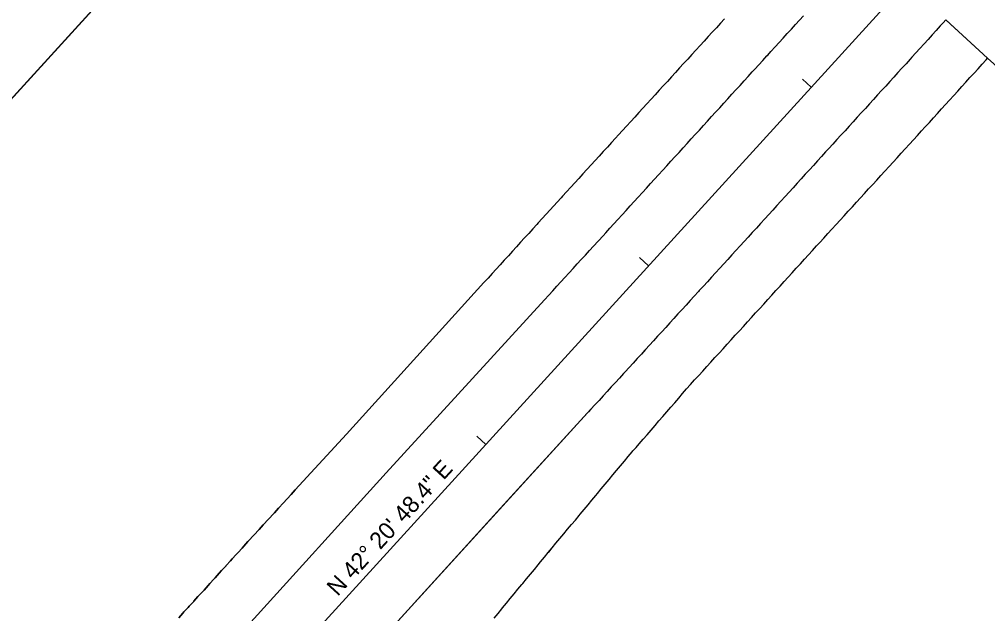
# Model space of a CAD drawing. Extents: x 1807040 to 1808827, y 913493 to 915218.
# Drawn here: x 1807609.2 to 1808009.9, y 913761.8 to 914007.6 of the extents above; entities that cross this region are included whole.
import ezdxf

# ---------------------------------------------------------------- set-up
doc = ezdxf.new("R2010")
doc.units = 0
for name, color, linetype in [('Old_Level_18', 7, 'Continuous'), ('Prop Dimension', 7, 'Continuous'), ('Prop EOT', 7, 'Continuous'), ('Prop Horizontal Alignment Direction Label', 7, 'Continuous'), ('Prop Horizontal Alignment Tick Small', 7, 'Continuous'), ('Scratch_Level_0', 7, 'Continuous'), ('Scratch_Level_1', 7, 'Continuous'), ('Scratch_Level_3', 7, 'Continuous')]:
    doc.layers.add(name, color=color, linetype=linetype)

msp = doc.modelspace()

# ---------------------------------------------------------------- linework, layer by layer
at = {"layer": 'Old_Level_18'}
msp.add_line((1808438.77, 914888.63), (1807428.35, 913780.01), dxfattribs=at)
at = {"layer": 'Prop Dimension'}
msp.add_line((1808082.8, 913925.07), (1808009.86, 913991.55), dxfattribs=at)
at = {"layer": 'Prop EOT'}
for p, q in [((1808009.86, 913991.55), (1807992.66, 914007.23)), ((1807683.94, 913668.92), (1807845.7, 913846.32))]:
    msp.add_line(p, q, dxfattribs=at)
for points in [[(1807900.98, 914007.89), (1807899.29, 914006.04), (1807897.61, 914004.19), (1807895.92, 914002.35), (1807894.24, 914000.5), (1807892.55, 913998.65), (1807890.87, 913996.81), (1807889.12, 913994.89), (1807887.44, 913993.04), (1807885.75, 913991.2), (1807884.07, 913989.35), (1807882.38, 913987.51), (1807880.7, 913985.66), (1807879.01, 913983.81), (1807877.33, 913981.97), (1807875.64, 913980.12), (1807873.95, 913978.27), (1807872.27, 913976.43), (1807870.58, 913974.58), (1807868.9, 913972.73), (1807867.21, 913970.89), (1807865.53, 913969.04), (1807863.84, 913967.19), (1807862.16, 913965.35), (1807860.47, 913963.5), (1807858.79, 913961.65), (1807857.1, 913959.81), (1807855.88, 913958.46), (1807854.19, 913956.62), (1807852.5, 913954.77), (1807850.82, 913952.93), (1807849.13, 913951.08), (1807847.45, 913949.23), (1807845.76, 913947.39), (1807844.07, 913945.54), (1807842.39, 913943.7), (1807840.7, 913941.85), (1807839.02, 913940), (1807837.33, 913938.16), (1807835.64, 913936.31), (1807833.96, 913934.47), (1807833.41, 913933.86)], [(1807992.51, 914007.37), (1807991.45, 914006.21), (1807990.25, 914004.89), (1807988.57, 914003.04), (1807986.89, 914001.19), (1807985.21, 913999.33), (1807983.53, 913997.48), (1807981.85, 913995.63), (1807980.17, 913993.78), (1807978.49, 913991.93), (1807977.77, 913991.14), (1807976.09, 913989.29), (1807974.41, 913987.44), (1807972.72, 913985.59), (1807971.04, 913983.75), (1807969.36, 913981.9), (1807967.67, 913980.05), (1807965.99, 913978.2), (1807964.31, 913976.35), (1807962.62, 913974.51), (1807960.94, 913972.66), (1807959.26, 913970.81), (1807957.57, 913968.96), (1807955.89, 913967.11), (1807954.21, 913965.26), (1807952.52, 913963.42), (1807950.84, 913961.57), (1807949.16, 913959.72), (1807947.47, 913957.87), (1807945.79, 913956.02), (1807944.11, 913954.17), (1807942.83, 913952.78), (1807941.15, 913950.93), (1807939.47, 913949.08), (1807937.79, 913947.23), (1807936.1, 913945.38), (1807934.42, 913943.53), (1807932.74, 913941.68), (1807931.06, 913939.83), (1807929.37, 913937.98), (1807927.69, 913936.13), (1807926.01, 913934.29), (1807924.33, 913932.44), (1807922.64, 913930.59), (1807920.96, 913928.74), (1807919.28, 913926.89), (1807917.6, 913925.04), (1807915.91, 913923.19), (1807915.84, 913923.11), (1807914.16, 913921.27), (1807912.47, 913919.42), (1807910.78, 913917.57), (1807909.1, 913915.73), (1807907.41, 913913.88), (1807905.73, 913912.04), (1807904.04, 913910.19), (1807902.36, 913908.34), (1807900.67, 913906.5), (1807898.98, 913904.65), (1807897.3, 913902.81), (1807895.61, 913900.96), (1807893.93, 913899.11), (1807892.24, 913897.27), (1807890.55, 913895.42), (1807890.16, 913894.99), (1807888.47, 913893.14), (1807886.79, 913891.29), (1807885.1, 913889.45), (1807883.41, 913887.6), (1807881.73, 913885.75), (1807880.04, 913883.91), (1807878.36, 913882.06), (1807876.67, 913880.21), (1807874.99, 913878.37), (1807873.3, 913876.52), (1807871.62, 913874.67), (1807869.93, 913872.83), (1807868.25, 913870.98), (1807866.56, 913869.13), (1807864.88, 913867.29), (1807863.19, 913865.44), (1807861.51, 913863.59), (1807859.82, 913861.75), (1807859.2, 913861.07), (1807857.51, 913859.22), (1807855.82, 913857.38), (1807854.14, 913855.54), (1807852.45, 913853.69), (1807850.76, 913851.85), (1807849.07, 913850), (1807847.38, 913848.16), (1807845.7, 913846.32), (1807844.74, 913845.29)], [(1807850.7, 913918.1), (1807851.83, 913919.34), (1807853.53, 913921.2), (1807855.21, 913923.05), (1807856.89, 913924.89), (1807858.58, 913926.74), (1807860.26, 913928.59), (1807861.95, 913930.44), (1807863.63, 913932.28), (1807865.31, 913934.13), (1807867, 913935.98), (1807868.68, 913937.83), (1807870.37, 913939.68), (1807872.05, 913941.52), (1807873.73, 913943.37), (1807875.42, 913945.22), (1807877.1, 913947.07), (1807878.79, 913948.91), (1807880.47, 913950.76), (1807882.15, 913952.61), (1807883.84, 913954.46), (1807885.52, 913956.31), (1807887.21, 913958.15), (1807888.89, 913960), (1807890.57, 913961.85), (1807892.26, 913963.7), (1807893.94, 913965.54), (1807895.63, 913967.39), (1807897.31, 913969.24), (1807898.99, 913971.09), (1807900.68, 913972.93), (1807902.36, 913974.78), (1807904.05, 913976.63), (1807905.73, 913978.48), (1807907.41, 913980.33), (1807909.1, 913982.17), (1807910.78, 913984.02), (1807912.47, 913985.87), (1807913.46, 913986.96), (1807915.15, 913988.81), (1807916.83, 913990.66), (1807918.52, 913992.51), (1807920.2, 913994.35), (1807921.89, 913996.2), (1807923.57, 913998.05), (1807925.26, 913999.89), (1807926.94, 914001.74), (1807928.63, 914003.59), (1807930.31, 914005.44), (1807931.99, 914007.28), (1807933.68, 914009.13)], [(1807863.1, 913829.08), (1807864.37, 913830.44), (1807865.68, 913832.01), (1807867.31, 913833.9), (1807868.95, 913835.79), (1807870.58, 913837.68), (1807872.22, 913839.57), (1807873.85, 913841.47), (1807875.49, 913843.36), (1807877.12, 913845.25), (1807878.76, 913847.14), (1807880.39, 913849.03), (1807882.02, 913850.92), (1807883.66, 913852.81), (1807885.29, 913854.71), (1807886.93, 913856.6), (1807888.61, 913858.45), (1807890.3, 913860.3), (1807891.98, 913862.15), (1807893.66, 913864), (1807895.35, 913865.84), (1807897.03, 913867.69), (1807898.71, 913869.54), (1807900.4, 913871.39), (1807902.08, 913873.24), (1807903.76, 913875.09), (1807905.45, 913876.93), (1807907.13, 913878.78), (1807908.81, 913880.63), (1807910.49, 913882.48), (1807912.18, 913884.33), (1807913.86, 913886.18), (1807915.54, 913888.03), (1807917.23, 913889.87), (1807918.91, 913891.72), (1807920.59, 913893.57), (1807922.28, 913895.42), (1807923.96, 913897.27), (1807925.64, 913899.12), (1807927.33, 913900.97), (1807929.01, 913902.81), (1807930.69, 913904.66), (1807932.38, 913906.51), (1807934.06, 913908.36), (1807935.74, 913910.21), (1807937.42, 913912.06), (1807939.11, 913913.91), (1807940.4, 913915.32), (1807942.08, 913917.17), (1807943.77, 913919.02), (1807945.45, 913920.86), (1807947.14, 913922.71), (1807948.83, 913924.56), (1807950.51, 913926.4), (1807952.2, 913928.25), (1807953.88, 913930.09), (1807955.57, 913931.94), (1807957.25, 913933.79), (1807958.94, 913935.63), (1807960.62, 913937.48), (1807962.31, 913939.33), (1807963.99, 913941.17), (1807965.68, 913943.02), (1807967.37, 913944.87), (1807969.05, 913946.71), (1807970.74, 913948.56), (1807972.42, 913950.41), (1807974.11, 913952.25), (1807975.79, 913954.1), (1807977.48, 913955.95), (1807979.16, 913957.79), (1807980.85, 913959.64), (1807982.53, 913961.48), (1807984.07, 913963.16), (1807985.75, 913965.01), (1807987.43, 913966.86), (1807989.11, 913968.71), (1807990.79, 913970.56), (1807992.47, 913972.41), (1807994.15, 913974.26), (1807995.84, 913976.11), (1807997.52, 913977.96), (1807999.2, 913979.81), (1808000.88, 913981.66), (1808002.56, 913983.51), (1808004.24, 913985.36), (1808005.92, 913987.21), (1808007.6, 913989.07), (1808009.29, 913990.92), (1808009.86, 913991.55)], [(1807833.41, 913933.86), (1807827.21, 913927.08), (1807825.53, 913925.24), (1807823.84, 913923.39), (1807823.3, 913922.8), (1807821.62, 913920.95), (1807819.94, 913919.1), (1807818.26, 913917.25), (1807816.58, 913915.4), (1807814.9, 913913.55), (1807813.21, 913911.7), (1807811.53, 913909.84), (1807809.85, 913907.99), (1807808.17, 913906.14), (1807806.49, 913904.29), (1807804.81, 913902.44), (1807803.13, 913900.59), (1807801.45, 913898.74), (1807744.5, 913836.05)], [(1807761.01, 913819.97), (1807826.53, 913891.66), (1807828.22, 913893.51), (1807829.9, 913895.35), (1807831.59, 913897.2), (1807833.28, 913899.04), (1807834.96, 913900.89), (1807836.65, 913902.73), (1807838.34, 913904.58), (1807840.02, 913906.42), (1807841.71, 913908.27), (1807843.4, 913910.11), (1807845.08, 913911.96), (1807846.77, 913913.8), (1807850.7, 913918.1)], [(1807675.11, 913760.08), (1807676.79, 913761.93), (1807677.3, 913762.49), (1807679, 913764.32), (1807679.5, 913764.86), (1807681.17, 913766.72), (1807681.41, 913766.98), (1807683.1, 913768.81), (1807683.88, 913769.66), (1807685.59, 913771.53), (1807687.27, 913773.38), (1807688.02, 913774.2), (1807689.69, 913776.06), (1807690.21, 913776.64), (1807691.87, 913778.49), (1807692.89, 913779.56), (1807694.56, 913781.42), (1807694.82, 913781.71), (1807696.49, 913783.56), (1807697.23, 913784.38), (1807698.93, 913786.2), (1807699.69, 913787.01), (1807701.35, 913788.87), (1807702.07, 913789.69), (1807703.74, 913791.55), (1807704.22, 913792.1), (1807705.92, 913793.93), (1807706.43, 913794.47), (1807708.12, 913796.31), (1807708.4, 913796.61), (1807710.09, 913798.45), (1807710.37, 913798.75), (1807712.04, 913800.6), (1807712.54, 913801.15), (1807714.23, 913802.98), (1807714.74, 913803.53), (1807716.42, 913805.38), (1807716.61, 913805.58), (1807718.29, 913807.42), (1807719.98, 913809.27), (1807721.67, 913811.11), (1807723.36, 913812.96), (1807744.5, 913836.05)], [(1807805.72, 913759.83), (1807807.27, 913761.8), (1807808.81, 913763.76), (1807809.13, 913764.16), (1807810.71, 913766.09), (1807812.3, 913768.02), (1807813.89, 913769.95), (1807815.48, 913771.88), (1807817.07, 913773.81), (1807817.47, 913774.3), (1807819.08, 913776.22), (1807820.68, 913778.14), (1807822.28, 913780.05), (1807823.89, 913781.97), (1807824.87, 913783.14), (1807826.45, 913785.07), (1807828.04, 913787), (1807829.63, 913788.93), (1807831.22, 913790.86), (1807832.84, 913792.83), (1807834.44, 913794.74), (1807836.05, 913796.66), (1807837.65, 913798.58), (1807839.25, 913800.5), (1807840.86, 913802.41), (1807841.31, 913802.95), (1807842.9, 913804.88), (1807844.5, 913806.8), (1807846.09, 913808.73), (1807847.68, 913810.65), (1807848.38, 913811.49), (1807849.98, 913813.4), (1807851.59, 913815.32), (1807853.2, 913817.23), (1807854.81, 913819.15), (1807856.33, 913820.96), (1807857.93, 913822.88), (1807859.53, 913824.81), (1807861.12, 913826.73), (1807862.72, 913828.65), (1807863.1, 913829.08)], [(1807703.77, 913756.85), (1807761.01, 913819.97)]]:
    msp.add_lwpolyline(points, dxfattribs=at)
at = {"layer": 'Prop Horizontal Alignment Tick Small'}
for p, q in [((1807936.89, 913979.58), (1807933.19, 913982.95)), ((1807869.53, 913905.67), (1807865.83, 913909.04)), ((1807802.17, 913831.77), (1807798.47, 913835.13))]:
    msp.add_line(p, q, dxfattribs=at)
at = {"layer": 'Scratch_Level_0'}
for p, q in [((1807900.98, 914007.89), (1807899.29, 914006.04)), ((1807931.99, 914007.28), (1807933.68, 914009.13)), ((1808009.86, 913991.55), (1807992.51, 914007.37)), ((1807897.61, 914004.19), (1807895.92, 914002.35)), ((1807899.29, 914006.04), (1807897.61, 914004.19)), ((1807889.12, 913994.89), (1807887.44, 913993.04)), ((1807892.55, 913998.65), (1807891.06, 913997.01)), ((1807887.44, 913993.04), (1807885.75, 913991.2)), ((1807915.15, 913988.81), (1807916.83, 913990.66)), ((1807916.83, 913990.66), (1807918.52, 913992.51)), ((1807918.52, 913992.51), (1807918.84, 913992.86)), ((1807918.84, 913992.86), (1807920.2, 913994.35)), ((1807882.38, 913987.51), (1807880.7, 913985.66)), ((1807880.7, 913985.66), (1807879.01, 913983.81)), ((1807909.1, 913982.17), (1807910.78, 913984.02)), ((1807907.41, 913980.33), (1807909.1, 913982.17)), ((1807872.27, 913976.43), (1807870.58, 913974.58)), ((1807902.36, 913974.78), (1807904.05, 913976.63)), ((1807893.94, 913965.54), (1807895.63, 913967.39)), ((1807888.89, 913960), (1807890.57, 913961.85)), ((1807852.5, 913954.77), (1807850.82, 913952.93)), ((1807854.19, 913956.62), (1807852.5, 913954.77)), ((1807845.76, 913947.39), (1807844.19, 913945.67)), ((1807847.45, 913949.23), (1807845.76, 913947.39)), ((1807844.19, 913945.67), (1807844.07, 913945.54)), ((1807840.7, 913941.85), (1807839.02, 913940)), ((1807856.89, 913924.89), (1807858.58, 913926.74)), ((1807850.7, 913918.1), (1807851.83, 913919.34)), ((1807867.88, 913870.58), (1807866.56, 913869.13)), ((1807845.7, 913846.32), (1807808.33, 913805.34)), ((1807808.33, 913805.34), (1807748.66, 913739.9))]:
    msp.add_line(p, q, dxfattribs=at)
for points in [[(1807992.51, 914007.37), (1807991.45, 914006.21), (1807990.25, 914004.89), (1807988.57, 914003.04), (1807986.89, 914001.19), (1807985.21, 913999.33), (1807983.53, 913997.48), (1807981.85, 913995.63), (1807980.17, 913993.78), (1807978.49, 913991.93), (1807977.77, 913991.14), (1807976.09, 913989.29), (1807974.41, 913987.44), (1807972.72, 913985.59), (1807971.04, 913983.75), (1807969.36, 913981.9), (1807967.67, 913980.05), (1807965.99, 913978.2), (1807964.31, 913976.35), (1807962.62, 913974.51), (1807960.94, 913972.66), (1807959.26, 913970.81), (1807957.57, 913968.96), (1807955.89, 913967.11), (1807954.21, 913965.26), (1807952.52, 913963.42), (1807950.84, 913961.57), (1807949.16, 913959.72), (1807947.47, 913957.87), (1807945.79, 913956.02), (1807944.11, 913954.17), (1807942.83, 913952.78), (1807941.15, 913950.93), (1807939.47, 913949.08), (1807937.79, 913947.23), (1807936.1, 913945.38), (1807934.42, 913943.53), (1807932.74, 913941.68), (1807931.06, 913939.83), (1807929.37, 913937.98), (1807927.69, 913936.13), (1807926.01, 913934.29), (1807924.33, 913932.44), (1807922.64, 913930.59), (1807920.96, 913928.74), (1807919.28, 913926.89), (1807917.6, 913925.04), (1807915.91, 913923.19), (1807915.84, 913923.11), (1807914.16, 913921.27), (1807912.47, 913919.42), (1807910.78, 913917.57), (1807909.1, 913915.73), (1807907.41, 913913.88), (1807905.73, 913912.04), (1807904.04, 913910.19), (1807902.36, 913908.34), (1807900.67, 913906.5), (1807898.98, 913904.65), (1807897.3, 913902.81), (1807895.61, 913900.96), (1807893.93, 913899.11), (1807892.24, 913897.27), (1807890.55, 913895.42), (1807890.16, 913894.99), (1807888.47, 913893.14), (1807886.79, 913891.29), (1807885.1, 913889.45), (1807883.41, 913887.6), (1807881.73, 913885.75), (1807880.04, 913883.91), (1807878.36, 913882.06), (1807876.67, 913880.21), (1807874.99, 913878.37), (1807873.3, 913876.52), (1807871.62, 913874.67), (1807869.93, 913872.83), (1807868.25, 913870.98), (1807867.88, 913870.58)], [(1807928.63, 914003.59), (1807930.31, 914005.44), (1807931.99, 914007.28)], [(1807920.2, 913994.35), (1807921.89, 913996.2), (1807923.57, 913998.05), (1807925.26, 913999.89), (1807926.94, 914001.74), (1807928.63, 914003.59)], [(1807895.92, 914002.35), (1807894.24, 914000.5), (1807892.55, 913998.65)], [(1807891.06, 913997.01), (1807890.87, 913996.81), (1807889.12, 913994.89)], [(1807885.75, 913991.2), (1807884.07, 913989.35), (1807882.38, 913987.51)], [(1807885.29, 913854.71), (1807886.93, 913856.6), (1807888.61, 913858.45), (1807890.3, 913860.3), (1807891.98, 913862.15), (1807893.66, 913864), (1807895.35, 913865.84), (1807897.03, 913867.69), (1807898.71, 913869.54), (1807900.4, 913871.39), (1807902.08, 913873.24), (1807903.76, 913875.09), (1807905.45, 913876.93), (1807907.13, 913878.78), (1807908.81, 913880.63), (1807910.49, 913882.48), (1807912.18, 913884.33), (1807913.86, 913886.18), (1807915.54, 913888.03), (1807917.23, 913889.87), (1807918.91, 913891.72), (1807920.59, 913893.57), (1807922.28, 913895.42), (1807923.96, 913897.27), (1807925.64, 913899.12), (1807927.33, 913900.97), (1807929.01, 913902.81), (1807930.69, 913904.66), (1807932.38, 913906.51), (1807934.06, 913908.36), (1807935.74, 913910.21), (1807937.42, 913912.06), (1807939.11, 913913.91), (1807940.4, 913915.32), (1807942.08, 913917.17), (1807943.77, 913919.02), (1807945.45, 913920.86), (1807947.14, 913922.71), (1807948.83, 913924.56), (1807950.51, 913926.4), (1807952.2, 913928.25), (1807953.88, 913930.09), (1807955.57, 913931.94), (1807957.25, 913933.79), (1807958.94, 913935.63), (1807960.62, 913937.48), (1807962.31, 913939.33), (1807963.99, 913941.17), (1807965.68, 913943.02), (1807967.37, 913944.87), (1807969.05, 913946.71), (1807970.74, 913948.56), (1807972.42, 913950.41), (1807974.11, 913952.25), (1807975.79, 913954.1), (1807977.48, 913955.95), (1807979.16, 913957.79), (1807980.85, 913959.64), (1807982.53, 913961.48), (1807984.07, 913963.16), (1807985.75, 913965.01), (1807987.43, 913966.86), (1807989.11, 913968.71), (1807990.79, 913970.56), (1807992.47, 913972.41), (1807994.15, 913974.26), (1807995.84, 913976.11), (1807997.52, 913977.96), (1807999.2, 913979.81), (1808000.88, 913981.66), (1808002.56, 913983.51), (1808004.24, 913985.36), (1808005.92, 913987.21), (1808007.6, 913989.07), (1808009.29, 913990.92), (1808009.86, 913991.55)], [(1807910.78, 913984.02), (1807912.47, 913985.87), (1807913.46, 913986.96), (1807915.15, 913988.81)], [(1807879.01, 913983.81), (1807877.33, 913981.97), (1807875.64, 913980.12), (1807873.95, 913978.27), (1807872.27, 913976.43)], [(1807904.05, 913976.63), (1807905.73, 913978.48), (1807907.41, 913980.33)], [(1807898.99, 913971.09), (1807900.68, 913972.93), (1807902.36, 913974.78)], [(1807867.21, 913970.89), (1807865.53, 913969.04), (1807863.84, 913967.19), (1807862.16, 913965.35)], [(1807870.58, 913974.58), (1807868.9, 913972.73), (1807867.21, 913970.89)], [(1807895.63, 913967.39), (1807897.31, 913969.24), (1807898.99, 913971.09)], [(1807862.16, 913965.35), (1807860.47, 913963.5), (1807858.79, 913961.65)], [(1807890.57, 913961.85), (1807892.26, 913963.7), (1807893.94, 913965.54)], [(1807858.79, 913961.65), (1807857.1, 913959.81), (1807855.88, 913958.46), (1807854.19, 913956.62)], [(1807883.84, 913954.46), (1807885.52, 913956.31), (1807887.21, 913958.15), (1807888.89, 913960)], [(1807850.82, 913952.93), (1807849.13, 913951.08), (1807847.45, 913949.23)], [(1807878.79, 913948.91), (1807880.47, 913950.76), (1807882.15, 913952.61), (1807883.84, 913954.46)], [(1807875.42, 913945.22), (1807877.1, 913947.07), (1807878.79, 913948.91)], [(1807844.07, 913945.54), (1807842.39, 913943.7), (1807840.7, 913941.85)], [(1807865.31, 913934.13), (1807867, 913935.98), (1807868.68, 913937.83), (1807870.37, 913939.68), (1807872.05, 913941.52), (1807873.73, 913943.37), (1807875.42, 913945.22)], [(1807839.02, 913940), (1807837.33, 913938.16), (1807835.64, 913936.31)], [(1807835.64, 913936.31), (1807833.96, 913934.47), (1807833.41, 913933.86)], [(1807833.41, 913933.86), (1807827.21, 913927.08), (1807825.53, 913925.24), (1807823.84, 913923.39), (1807823.3, 913922.8), (1807821.62, 913920.95), (1807819.94, 913919.1), (1807818.26, 913917.25), (1807816.58, 913915.4), (1807814.9, 913913.55), (1807813.21, 913911.7), (1807811.53, 913909.84), (1807809.85, 913907.99), (1807808.17, 913906.14), (1807806.49, 913904.29), (1807804.81, 913902.44), (1807803.13, 913900.59), (1807801.45, 913898.74), (1807744.5, 913836.05)], [(1807858.58, 913926.74), (1807860.26, 913928.59), (1807861.95, 913930.44), (1807863.63, 913932.28), (1807865.31, 913934.13)], [(1807851.83, 913919.34), (1807853.53, 913921.2), (1807855.21, 913923.05), (1807856.89, 913924.89)], [(1807761.01, 913819.97), (1807826.53, 913891.66), (1807828.22, 913893.51), (1807829.9, 913895.35), (1807831.59, 913897.2), (1807833.28, 913899.04), (1807834.96, 913900.89), (1807836.65, 913902.73), (1807838.34, 913904.58), (1807840.02, 913906.42), (1807841.71, 913908.27), (1807843.4, 913910.11), (1807845.08, 913911.96), (1807846.77, 913913.8), (1807850.7, 913918.1)], [(1807866.56, 913869.13), (1807864.88, 913867.29), (1807863.19, 913865.44), (1807861.51, 913863.59), (1807859.82, 913861.75), (1807859.2, 913861.07), (1807857.51, 913859.22), (1807855.82, 913857.38), (1807854.14, 913855.54), (1807852.45, 913853.69), (1807850.76, 913851.85), (1807849.07, 913850), (1807847.38, 913848.16), (1807845.7, 913846.32)], [(1807863.1, 913829.08), (1807864.37, 913830.44), (1807865.68, 913832.01), (1807867.31, 913833.9), (1807868.95, 913835.79), (1807870.58, 913837.68), (1807872.22, 913839.57), (1807873.85, 913841.47), (1807875.49, 913843.36), (1807877.12, 913845.25), (1807878.76, 913847.14), (1807880.39, 913849.03), (1807882.02, 913850.92), (1807883.66, 913852.81), (1807885.29, 913854.71)], [(1807744.5, 913836.05), (1807723.36, 913812.96), (1807721.67, 913811.11), (1807719.98, 913809.27), (1807718.29, 913807.42), (1807716.61, 913805.58), (1807716.42, 913805.38), (1807714.74, 913803.53), (1807714.23, 913802.98), (1807712.54, 913801.15), (1807712.04, 913800.6), (1807710.37, 913798.75), (1807710.09, 913798.45), (1807708.4, 913796.61), (1807708.12, 913796.31), (1807706.43, 913794.47), (1807705.92, 913793.93), (1807704.22, 913792.1), (1807703.74, 913791.55), (1807702.07, 913789.69), (1807701.35, 913788.87), (1807699.69, 913787.01), (1807698.93, 913786.2), (1807697.23, 913784.38), (1807696.49, 913783.56), (1807694.82, 913781.71), (1807694.56, 913781.42), (1807692.89, 913779.56), (1807691.87, 913778.49), (1807690.21, 913776.64), (1807689.69, 913776.06), (1807688.02, 913774.2), (1807687.27, 913773.38), (1807685.59, 913771.53), (1807683.88, 913769.66), (1807683.1, 913768.81), (1807681.41, 913766.98), (1807681.17, 913766.72), (1807679.5, 913764.86), (1807679, 913764.32), (1807677.3, 913762.49), (1807676.79, 913761.93), (1807675.11, 913760.08)], [(1807828.22, 913787.21), (1807829.63, 913788.93), (1807831.22, 913790.86), (1807832.84, 913792.83), (1807834.44, 913794.74), (1807836.05, 913796.66), (1807837.65, 913798.58), (1807839.25, 913800.5), (1807840.86, 913802.41), (1807841.31, 913802.95), (1807842.9, 913804.88), (1807844.5, 913806.8), (1807846.09, 913808.73), (1807847.68, 913810.65), (1807848.38, 913811.49), (1807849.98, 913813.4), (1807851.59, 913815.32), (1807853.2, 913817.23), (1807854.81, 913819.15), (1807856.33, 913820.96), (1807857.93, 913822.88), (1807859.53, 913824.81), (1807861.12, 913826.73), (1807862.72, 913828.65), (1807863.1, 913829.08)], [(1807703.77, 913756.85), (1807761.01, 913819.97)], [(1807805.72, 913759.83), (1807807.27, 913761.8), (1807808.81, 913763.76), (1807809.13, 913764.16), (1807810.71, 913766.09), (1807812.3, 913768.02), (1807813.89, 913769.95), (1807815.48, 913771.88), (1807817.07, 913773.81), (1807817.47, 913774.3), (1807819.08, 913776.22), (1807820.68, 913778.14), (1807822.28, 913780.05), (1807823.89, 913781.97), (1807824.87, 913783.14), (1807826.45, 913785.07), (1807828.04, 913787), (1807828.22, 913787.21)]]:
    msp.add_lwpolyline(points, dxfattribs=at)
at = {"layer": 'Scratch_Level_1'}
for points in [[(1807040.33, 914133.66), (1807040.33, 914133.66), (1807428.35, 913780.01), (1808256.27, 914688.39), (1807868.25, 915042.04)], [(1807489.01, 913846.57), (1807877.03, 913492.93), (1808826.79, 914534.98), (1808438.77, 914888.63)]]:
    msp.add_lwpolyline(points, close=True, dxfattribs=at)
at = {"layer": 'Scratch_Level_3'}
msp.add_line((1807667.44, 913683.95), (1808610.51, 914718.66), dxfattribs=at)

# ---------------------------------------------------------------- texts
at = {"layer": 'Prop Horizontal Alignment Direction Label'}
msp.add_text('N 42%%d 20\' 48.4" E', height=7, rotation=47.6532, dxfattribs=at).set_placement((1807740.92, 913768.64))

doc.saveas('drawing.dxf')
